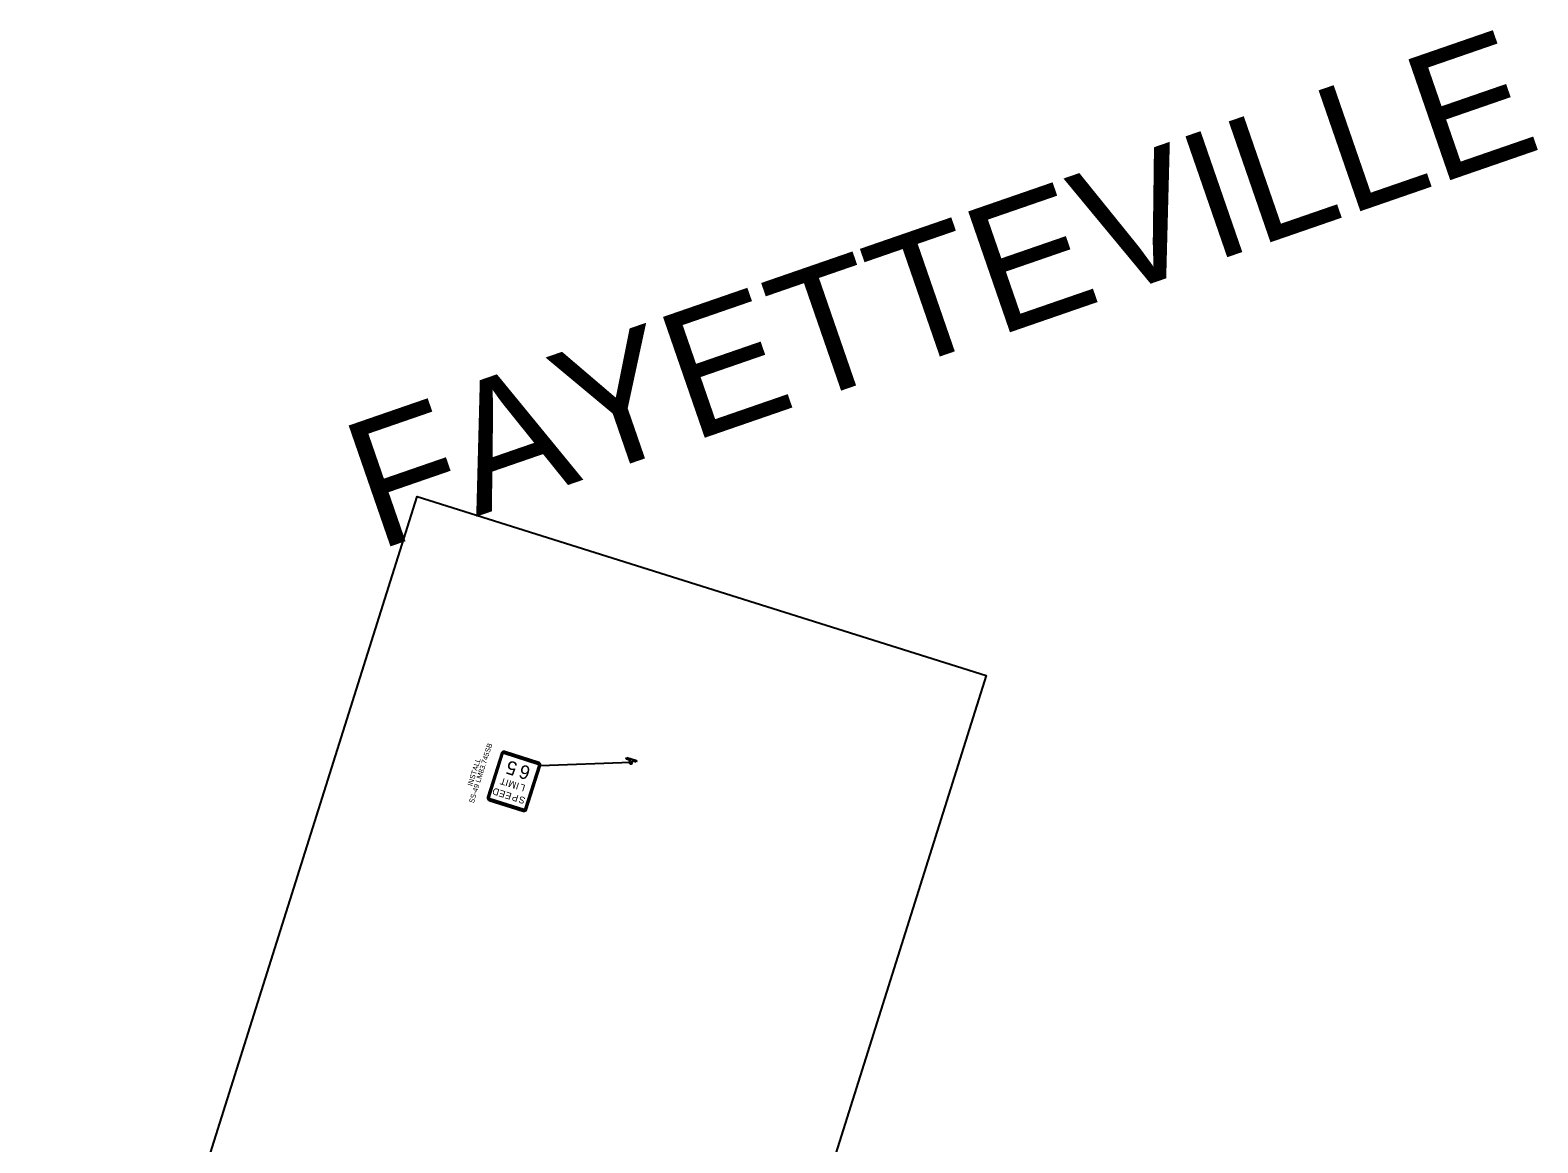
# Model space of a CAD drawing. Extents: x 639753 to 654136, y 407791 to 434220.
# Drawn here: x 643445 to 646982, y 431610 to 434220 of the extents above; entities that cross this region are included whole.
import ezdxf

# ---------------------------------------------------------------- set-up
doc = ezdxf.new("R2010")
doc.units = 0
for name, color, linetype in [('C-TRAF-SYMB', 7, 'Continuous'), ('R_Dimension', 7, 'Continuous'), ('R_No Plot', 7, 'Continuous'), ('S_SIGN', 7, 'Continuous')]:
    doc.layers.add(name, color=color, linetype=linetype)

msp = doc.modelspace()

# ---------------------------------------------------------------- linework, layer by layer
at = {"layer": 'C-TRAF-SYMB'}
for p, q in [((644843.4, 432510.1), (644844.5, 432513.9)), ((644854, 432507), (644843.4, 432510.1)), ((644844.5, 432513.9), (644867.6, 432507.2)), ((644854, 432506.9), (644854, 432507)), ((644866.5, 432503.4), (644855.7, 432506.5)), ((644855.7, 432506.5), (644855.7, 432506.4)), ((644867.6, 432507.2), (644866.5, 432503.4))]:
    msp.add_line(p, q, dxfattribs=at)
for start, end in [(163.877, 61.5571), (87.7391, 163.877)]:
    msp.add_arc((644853.8, 432502.9), 4, start, end, dxfattribs=at)
at = {"layer": 'R_Dimension'}
msp.add_line((644641.8, 432495), (644853.8, 432502.9), dxfattribs=at)
at = {"layer": 'R_No Plot'}
msp.add_lwpolyline([(643444.8, 430243.3), (644352.7, 433126.6), (645688.1, 432706.1), (644783, 429831.8), (644746.9, 429842.9)], close=True, dxfattribs=at)
at = {"layer": 'S_SIGN'}
for p, q in [((644550.3, 432523.8), (644517.8, 432420.8)), ((644637.9, 432502.5), (644557.8, 432527.7)), ((644609.4, 432392), (644641.8, 432495)), ((644521.8, 432413.3), (644601.9, 432388.1))]:
    msp.add_line(p, q, dxfattribs=at)
for points in [[(644551.7, 432523.4), (644519.3, 432420.4)], [(644521.7, 432419.6), (644554.1, 432522.6)], [(644551.7, 432523.4), (644551.7, 432523.4), (644551.7, 432523.4)], [(644556.6, 432523.9), (644636.7, 432498.7)], [(644637.5, 432501.1), (644557.4, 432526.3)], [(644638, 432496.2), (644605.6, 432393.2)], [(644608, 432392.4), (644640.4, 432495.4)], [(644637.5, 432501.1), (644637.5, 432501.1), (644637.5, 432501.1)], [(644522.2, 432414.7), (644602.3, 432389.5)], [(644522.2, 432414.7), (644522.2, 432414.7), (644522.2, 432414.7)], [(644603.1, 432391.9), (644523, 432417.1)], [(644608, 432392.4), (644608, 432392.4), (644608, 432392.4)]]:
    msp.add_lwpolyline(points, dxfattribs=at)
for centre, radius, start, end in [((644556, 432522), 6, 72.5214, 162.5216), ((644556, 432522), 4.5, 72.5214, 162.5216), ((644556, 432522), 2, 72.5214, 162.5216), ((644636.1, 432496.8), 2, 342.5212, 72.5214), ((644636.1, 432496.8), 4.5, 342.5212, 72.5214), ((644636.1, 432496.8), 6, 342.5212, 72.5214), ((644523.6, 432419), 6, 162.5213, 252.5216), ((644523.6, 432419), 4.5, 162.5213, 252.5216), ((644523.6, 432419), 2, 162.5213, 252.5216), ((644603.7, 432393.8), 6, 252.5216, 342.5212), ((644603.7, 432393.8), 4.5, 252.5216, 342.5212), ((644603.7, 432393.8), 2, 252.5216, 342.5212)]:
    msp.add_arc(centre, radius, start, end, dxfattribs=at)

# ---------------------------------------------------------------- texts
at = {"layer": 'R_Dimension'}
for s, p in [('SS-49 LM83.745SB', (644485.4, 432405.6)), ('INSTALL', (644481.9, 432445.9))]:
    msp.add_text(s, height=12, rotation=72.5213, dxfattribs=at).set_placement(p)
at = {"layer": 'R_No Plot'}
msp.add_text('FAYETTEVILLE', height=300, rotation=19.061, dxfattribs=at).set_placement((644259, 432998.5))
at = {"layer": 'S_SIGN'}
for s, height, p in [('5', 32, (644590.4, 432500.7)), ('6', 32, (644621, 432491.1)), ('D', 16, (644547.1, 432438.9)), ('E', 16, (644561.4, 432434.3)), ('T', 16, (644563.2, 432463.2)), ('I', 16, (644568.9, 432461.3)), ('M', 16, (644586.9, 432455.7)), ('I', 16, (644593.4, 432453.6)), ('L', 16, (644607.7, 432449.1)), ('E', 16, (644575.8, 432429.8)), ('P', 16, (644591.9, 432424.8)), ('S', 16, (644607.9, 432419.7))]:
    msp.add_text(s, height=height, rotation=162.5213, dxfattribs=at).set_placement(p)

doc.saveas('drawing.dxf')
